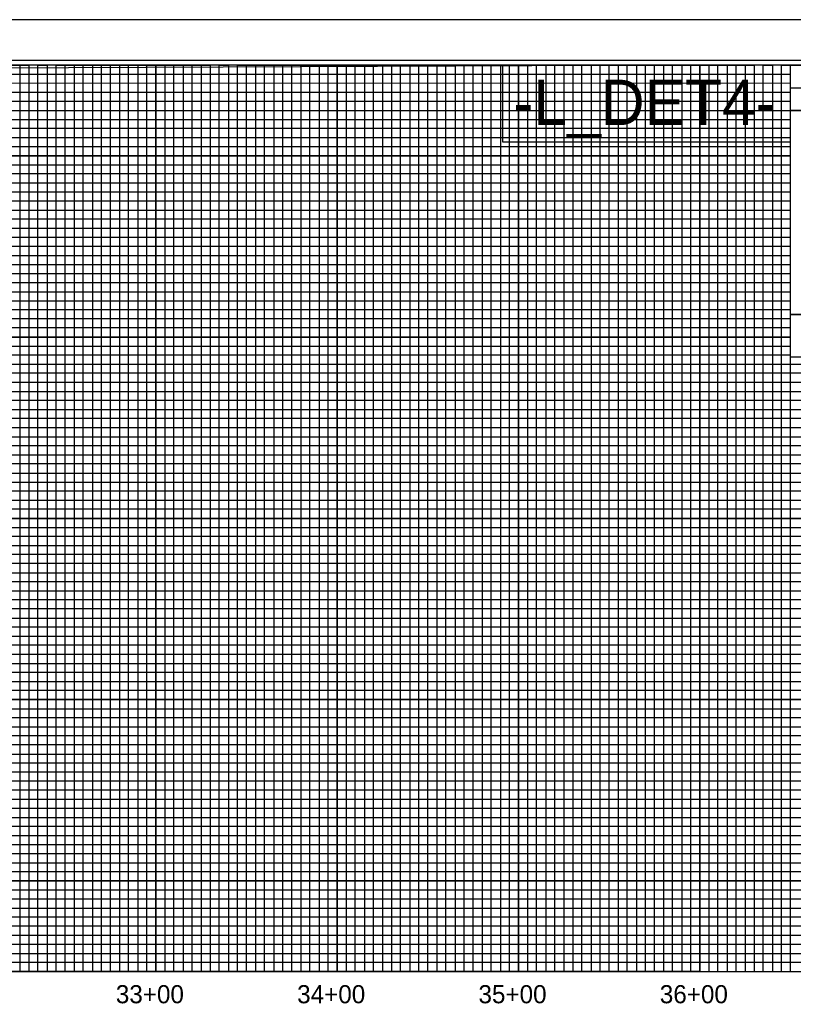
# Model space of a CAD drawing. Extents: x 497599 to 513368, y 404140 to 476034.
# Drawn here: x 506734 to 507160, y 439315 to 439861 of the extents above; entities that cross this region are included whole.
import ezdxf

# ---------------------------------------------------------------- set-up
doc = ezdxf.new("R2010")
doc.units = 0
for name, color, linetype in [('Exist Vertical Profile Vertical Axis Label', 7, 'Continuous'), ('Old_Level_1', 7, 'Continuous'), ('Prop Grid Mask', 7, 'Continuous'), ('Sheet Cutting Line CELL', 7, 'Continuous'), ('Sheet DOT Grid CELL', 7, 'Continuous'), ('Sheet Layout Profile Border Port 1', 7, 'Continuous'), ('Sheet Plot Border Inside CELL', 7, 'Continuous'), ('Sheet Plot Border Outside CELL', 7, 'Continuous'), ('Sheet Profile CELL', 7, 'Continuous'), ('Sheet Profile Grid Major CELL', 7, 'Continuous'), ('Sheet Profile Grid Middle CELL', 7, 'Continuous'), ('Sheet Profile Grid Minor CELL', 7, 'Continuous'), ('Sheet Sticker Exception Certification CELL', 7, 'Continuous')]:
    doc.layers.add(name, color=color, linetype=linetype)

msp = doc.modelspace()

# ---------------------------------------------------------------- linework, layer by layer
at = {"layer": 'Prop Grid Mask'}
msp.add_lwpolyline([(507158.63, 439836.14), (506999.77, 439836.14), (506999.77, 439793.82), (507158.63, 439793.82)], close=True, dxfattribs=at)
at = {"layer": 'Sheet Cutting Line CELL'}
msp.add_line((507375.68, 439861.14), (505691.68, 439861.14), dxfattribs=at)
at = {"layer": 'Sheet DOT Grid CELL'}
for p, q in [((506758.68, 439336.14), (506758.68, 439836.14)), ((506808.68, 439336.14), (506808.68, 439836.14)), ((506858.68, 439336.14), (506858.68, 439836.14)), ((506908.68, 439336.14), (506908.68, 439836.14)), ((506958.68, 439336.14), (506958.68, 439836.14)), ((507008.68, 439336.14), (507008.68, 439836.14)), ((507058.68, 439336.14), (507058.68, 439836.14)), ((507108.68, 439336.14), (507108.68, 439836.14)), ((507158.63, 439786.14), (505858.68, 439786.14)), ((507158.63, 439736.14), (505858.68, 439736.14)), ((507158.68, 439336.14), (507158.68, 439698.59)), ((507158.68, 439686.14), (505858.68, 439686.14)), ((507358.68, 439636.14), (505858.68, 439636.14)), ((507358.68, 439586.14), (505858.68, 439586.14)), ((507358.68, 439536.14), (505858.68, 439536.14)), ((507358.68, 439486.14), (505858.68, 439486.14)), ((507358.68, 439436.14), (505858.68, 439436.14)), ((507358.68, 439386.14), (505858.68, 439386.14))]:
    msp.add_line(p, q, dxfattribs=at)
at = {"layer": 'Sheet Layout Profile Border Port 1'}
msp.add_lwpolyline([(505908.68, 439831.14), (507058.68, 439836.14), (507108.68, 439836.14), (507108.68, 439786.14), (507108.68, 439336.14), (505908.68, 439336.14)], close=True, dxfattribs=at)
at = {"layer": 'Sheet Plot Border Inside CELL'}
msp.add_lwpolyline([(505704.68, 438783.59), (507371.18, 438783.59), (507371.18, 439838.69), (505704.68, 439838.69)], close=True, dxfattribs=at)
at = {"layer": 'Sheet Plot Border Outside CELL'}
msp.add_lwpolyline([(505691.68, 438761.14), (507375.68, 438761.14), (507375.68, 439861.14), (505691.68, 439861.14)], close=True, dxfattribs=at)
at = {"layer": 'Sheet Profile CELL'}
for p, q in [((507158.63, 439823.59), (507358.68, 439823.59)), ((505858.68, 439336.14), (507358.68, 439336.14))]:
    msp.add_line(p, q, dxfattribs=at)
for points in [[(507358.68, 439836.14), (505858.68, 439836.14), (505858.68, 438786.14), (507358.68, 438786.14)], [(507158.63, 439836.14), (507358.68, 439836.14), (507358.68, 439811.09), (507158.63, 439811.09)], [(507158.63, 439811.09), (507258.68, 439811.09), (507258.68, 439698.59), (507158.63, 439698.59)]]:
    msp.add_lwpolyline(points, close=True, dxfattribs=at)
at = {"layer": 'Sheet Profile Grid Major CELL'}
for points in [[(506708.68, 439336.14), (506758.68, 439336.14), (506758.68, 439836.14), (506808.68, 439836.14), (506808.68, 439336.14), (506858.68, 439336.14), (506858.68, 439836.14), (506908.68, 439836.14), (506908.68, 439336.14), (506958.68, 439336.14), (506958.68, 439836.14), (507008.68, 439836.14), (507008.68, 439336.14), (507058.68, 439336.14), (507058.68, 439836.14), (507108.68, 439836.14), (507108.68, 439336.14), (507158.68, 439336.14), (507158.68, 439836.14), (507184.98, 439836.14)], [(505858.68, 439786.14), (507158.68, 439786.14)], [(507158.68, 439736.14), (505858.68, 439736.14), (505858.68, 439686.14), (507158.68, 439686.14)], [(507358.68, 439636.14), (505858.68, 439636.14), (505858.68, 439586.14), (507358.68, 439586.14)], [(507358.68, 439536.14), (505858.68, 439536.14), (505858.68, 439486.14), (507358.68, 439486.14)], [(507358.68, 439436.14), (505858.68, 439436.14), (505858.68, 439436.14), (505858.68, 439386.14), (507358.68, 439386.14)]]:
    msp.add_lwpolyline(points, dxfattribs=at)
at = {"layer": 'Sheet Profile Grid Middle CELL'}
msp.add_line((505858.68, 439811.14), (507158.63, 439811.14), dxfattribs=at)
for points in [[(506683.68, 439836.14), (506733.68, 439836.14), (506733.68, 439336.14), (506783.68, 439336.14), (506783.68, 439836.14), (506833.68, 439836.14), (506833.68, 439336.14), (506883.68, 439336.14), (506883.68, 439836.14), (506933.68, 439836.14), (506933.68, 439336.14), (506983.68, 439336.14), (506983.68, 439836.14), (507033.68, 439836.14), (507033.68, 439336.14), (507083.68, 439336.14), (507083.68, 439836.14), (507133.68, 439836.14), (507133.68, 439336.14), (507183.68, 439336.14), (507183.68, 439675.09)], [(507158.68, 439761.14), (505858.68, 439761.14), (505858.68, 439711.14), (507158.68, 439711.14)], [(507358.68, 439661.14), (505858.68, 439661.14), (505858.68, 439611.14), (507183.68, 439611.14)], [(507358.68, 439561.14), (505858.68, 439561.14), (505858.68, 439511.14), (507358.68, 439511.14)], [(507358.68, 439461.14), (505858.68, 439461.14), (505858.68, 439411.14), (507358.68, 439411.14)], [(507358.68, 439361.14), (505858.68, 439361.14)]]:
    msp.add_lwpolyline(points, dxfattribs=at)
at = {"layer": 'Sheet Profile Grid Minor CELL'}
for p, q in [((505908.68, 439831.14), (507158.68, 439831.14)), ((507158.68, 439826.14), (505908.68, 439825.79)), ((505908.68, 439821.14), (507158.68, 439821.14)), ((507158.63, 439701.14), (505908.68, 439701.14)), ((507158.68, 439696.14), (505908.68, 439696.14)), ((507158.68, 439691.14), (505908.68, 439691.14)), ((505908.68, 439681.14), (507158.68, 439681.14)), ((507158.68, 439676.14), (505908.68, 439676.14)), ((505908.68, 439671.14), (507308.68, 439671.14)), ((507308.68, 439651.14), (505908.68, 439651.14)), ((505908.68, 439646.14), (507308.68, 439646.14)), ((507308.68, 439626.14), (505908.68, 439626.14)), ((505908.68, 439621.14), (507308.68, 439621.14)), ((507308.68, 439601.14), (505908.68, 439601.14)), ((505908.68, 439596.14), (507308.68, 439596.14)), ((507308.68, 439591.14), (505908.68, 439591.14)), ((505908.68, 439581.14), (507308.68, 439581.14)), ((507308.68, 439576.14), (505908.68, 439576.14)), ((505908.68, 439571.14), (507308.68, 439571.14)), ((507308.68, 439566.14), (505908.68, 439566.14)), ((505908.68, 439556.14), (507308.68, 439556.14)), ((507308.68, 439551.14), (505908.68, 439551.14)), ((505908.68, 439546.14), (507308.68, 439546.14)), ((507308.68, 439541.14), (505908.68, 439541.14)), ((505908.68, 439531.14), (507308.68, 439531.14)), ((507308.68, 439526.14), (505908.68, 439526.14)), ((505908.68, 439521.14), (507308.68, 439521.14)), ((507308.68, 439516.14), (505908.68, 439516.14)), ((505908.68, 439506.14), (507308.68, 439506.14)), ((507308.68, 439501.14), (505908.68, 439501.14)), ((505908.68, 439496.14), (507308.68, 439496.14)), ((507308.68, 439491.14), (505908.68, 439491.14)), ((505908.68, 439481.14), (507308.68, 439481.14)), ((507308.68, 439476.14), (505908.68, 439476.14)), ((505908.68, 439471.14), (507308.68, 439471.14)), ((507308.68, 439466.14), (505908.68, 439466.14)), ((505908.68, 439456.14), (507308.68, 439456.14)), ((507308.68, 439451.14), (505908.68, 439451.14)), ((507308.68, 439446.14), (505908.68, 439446.14)), ((507308.68, 439441.14), (505908.68, 439441.14)), ((505908.68, 439431.14), (507308.68, 439431.14)), ((507308.68, 439426.14), (505908.68, 439426.14)), ((505908.68, 439421.14), (507308.68, 439421.14)), ((507308.68, 439416.14), (505908.68, 439416.14)), ((505908.68, 439406.14), (507308.68, 439406.14)), ((507308.68, 439401.14), (505908.68, 439401.14)), ((505908.68, 439396.14), (507308.68, 439396.14)), ((507308.68, 439391.14), (505908.68, 439391.14)), ((505908.68, 439381.14), (507308.68, 439381.14)), ((507308.68, 439376.14), (505908.68, 439376.14)), ((505908.68, 439371.14), (507308.68, 439371.14)), ((507308.68, 439366.14), (505908.68, 439366.14)), ((505908.68, 439356.14), (507308.68, 439356.14)), ((507308.68, 439351.14), (505908.68, 439351.14)), ((505908.68, 439346.14), (507308.68, 439346.14))]:
    msp.add_line(p, q, dxfattribs=at)
for points in [[(506728.68, 439836.14), (506738.68, 439836.14), (506738.68, 439336.14), (506743.68, 439336.14)], [(506743.68, 439336.14), (506743.68, 439836.14), (506748.68, 439836.14), (506748.68, 439336.14), (506753.68, 439336.14), (506753.68, 439836.14), (506763.68, 439836.14), (506763.68, 439336.14), (506768.68, 439336.14), (506768.68, 439836.14), (506773.68, 439836.14), (506773.68, 439336.14), (506778.68, 439336.14), (506778.68, 439836.14), (506788.68, 439836.14), (506788.68, 439336.14), (506793.68, 439336.14), (506793.68, 439836.14), (506798.68, 439836.14), (506798.68, 439336.14), (506803.68, 439336.14), (506803.68, 439836.14), (506813.68, 439836.14), (506813.68, 439336.14), (506818.68, 439336.14), (506818.68, 439836.14), (506823.68, 439836.14), (506823.68, 439336.14), (506828.68, 439336.14), (506828.68, 439836.14), (506838.68, 439836.14), (506838.68, 439336.14), (506843.68, 439336.14), (506843.68, 439836.14), (506848.68, 439836.14), (506848.68, 439336.14), (506853.68, 439336.14), (506853.68, 439836.14), (506863.68, 439836.14), (506863.68, 439336.14), (506868.68, 439336.14), (506868.68, 439836.14), (506873.68, 439836.14), (506873.68, 439336.14), (506878.68, 439336.14), (506878.68, 439836.14), (506888.68, 439836.14), (506888.68, 439336.14), (506893.68, 439336.14), (506893.68, 439836.14), (506898.68, 439836.14), (506898.68, 439336.14), (506903.68, 439336.14), (506903.68, 439836.14), (506913.68, 439836.14), (506913.68, 439336.14), (506918.68, 439336.14), (506918.68, 439836.14), (506923.68, 439836.14), (506923.68, 439336.14), (506928.68, 439336.14), (506928.68, 439836.14), (506938.68, 439836.14), (506938.68, 439336.14), (506943.68, 439336.14), (506943.68, 439836.14), (506948.68, 439836.14), (506948.68, 439336.14), (506953.68, 439336.14), (506953.68, 439836.14), (506963.68, 439836.14), (506963.68, 439336.14), (506968.68, 439336.14), (506968.68, 439836.14), (506973.68, 439836.14), (506973.68, 439336.14), (506978.68, 439336.14), (506978.68, 439836.14), (506988.68, 439836.14), (506988.68, 439336.14), (506993.68, 439336.14), (506993.68, 439836.14), (506998.68, 439836.14), (506998.68, 439336.14), (507003.68, 439336.14), (507003.68, 439836.14), (507013.68, 439836.14), (507013.68, 439336.14), (507018.68, 439336.14), (507018.68, 439836.14), (507023.68, 439836.14), (507023.68, 439336.14), (507028.68, 439336.14), (507028.68, 439836.14), (507038.68, 439836.14), (507038.68, 439336.14), (507043.68, 439336.14), (507043.68, 439836.14), (507048.68, 439836.14), (507048.68, 439336.14)], [(507048.68, 439336.14), (507053.68, 439336.14), (507053.68, 439836.14), (507063.68, 439836.14), (507063.68, 439336.14), (507068.68, 439336.14), (507068.68, 439836.14), (507073.68, 439836.14), (507073.68, 439336.14), (507078.68, 439336.14), (507078.68, 439836.14), (507088.68, 439836.14), (507088.68, 439336.14), (507093.68, 439336.14), (507093.68, 439836.14), (507098.68, 439836.14), (507098.68, 439336.14), (507103.68, 439336.14), (507103.68, 439836.14), (507113.68, 439836.14), (507113.68, 439336.14), (507118.68, 439336.14), (507118.68, 439836.14), (507123.68, 439836.14), (507123.68, 439336.14), (507128.68, 439336.14), (507128.68, 439836.14), (507138.68, 439836.14), (507138.68, 439336.14), (507143.68, 439336.14), (507143.68, 439836.14), (507148.68, 439836.14), (507148.68, 439336.14), (507153.68, 439336.14), (507153.68, 439836.14), (507163.68, 439836.14)], [(507158.68, 439816.14), (505908.68, 439816.14), (505908.68, 439806.14), (507158.68, 439806.14)], [(507158.63, 439801.14), (505908.68, 439801.14), (505908.68, 439796.14), (507158.68, 439796.14)], [(507158.68, 439791.14), (505908.68, 439791.14), (505908.68, 439781.14), (507158.68, 439781.14)], [(507158.68, 439776.14), (505908.68, 439776.14), (505908.68, 439771.14), (507158.68, 439771.14)], [(507158.68, 439766.14), (505908.68, 439766.14), (505908.68, 439756.14), (507158.68, 439756.14)], [(507158.68, 439751.14), (505908.68, 439751.14), (505908.68, 439746.14), (507158.68, 439746.14)], [(507158.68, 439741.14), (505908.68, 439741.14), (505908.68, 439731.14), (507158.68, 439731.14)], [(507158.68, 439726.04), (505908.78, 439726.04), (505908.78, 439721.14), (507158.68, 439721.14)], [(507158.68, 439716.14), (505908.68, 439716.14), (505908.68, 439706.14), (507158.68, 439706.14)], [(507308.68, 439666.14), (505908.68, 439666.14), (505908.68, 439656.14), (507308.68, 439656.14)], [(507308.68, 439641.14), (505908.68, 439641.14), (505908.68, 439631.14), (507308.68, 439631.14)], [(507308.68, 439616.14), (505908.68, 439616.14), (505908.68, 439606.14), (507308.68, 439606.14)], [(507308.68, 439341.14), (505908.68, 439341.14)]]:
    msp.add_lwpolyline(points, dxfattribs=at)
at = {"layer": 'Sheet Sticker Exception Certification CELL'}
for p, q in [((507158.63, 439675.09), (507158.63, 439698.59)), ((507158.63, 439698.59), (507358.67, 439698.59)), ((507158.63, 439675.09), (507158.63, 439698.59)), ((507158.63, 439698.59), (507358.67, 439698.59)), ((507358.67, 439675.09), (507158.63, 439675.09)), ((507358.67, 439675.09), (507158.63, 439675.09))]:
    msp.add_line(p, q, dxfattribs=at)

# ---------------------------------------------------------------- texts
at = {"layer": 'Exist Vertical Profile Vertical Axis Label'}
for s, p in [('33+00', (506786.61, 439318.64)), ('34+00', (506886.61, 439318.64)), ('35+00', (506986.61, 439318.64)), ('36+00', (507086.61, 439318.64))]:
    msp.add_text(s, height=10, dxfattribs=at).set_placement(p)
at = {"layer": 'Old_Level_1'}
msp.add_text('-L_DET4-', height=25, dxfattribs=at).set_placement((507005.77, 439803.11))

doc.saveas('drawing.dxf')
